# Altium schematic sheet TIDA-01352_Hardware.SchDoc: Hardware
size 431 x 279 mm; Date: Not shown in title block; ApprovedBy: Not shown in title block; CheckedBy: Not shown in title block; Author: Not shown in title block; CompanyName: Not shown in title block; DrawnBy: Sanjay Pithadia; Engineer: Sanjay Pithadia; Organization: Not shown in title block; Address1: Not shown in title block; Address2: Not shown in title block; Address3: Not shown in title block; Address4: Not shown in title block; DocumentNumber: 1; Revision: Use project parameter SCH_Rev; SheetNumber: 9; SheetTotal: 9; PageSetup: Record=PageOptions¦CenterHorizontal=True¦CenterVertical=True¦PrintScale=1.00¦XCorrection=1.00¦YCorrection=1.00¦PrintKind=0¦BorderSize=5000000¦LeftOffset=0¦BottomOffset=0¦Orientation=2¦PaperLength=1000¦PaperWidth=1000¦Scale=100¦PaperSource=15¦PrintQuality=600¦MediaType=1¦DitherType=10¦PaperKind=Letter¦PrintScaleMode=1
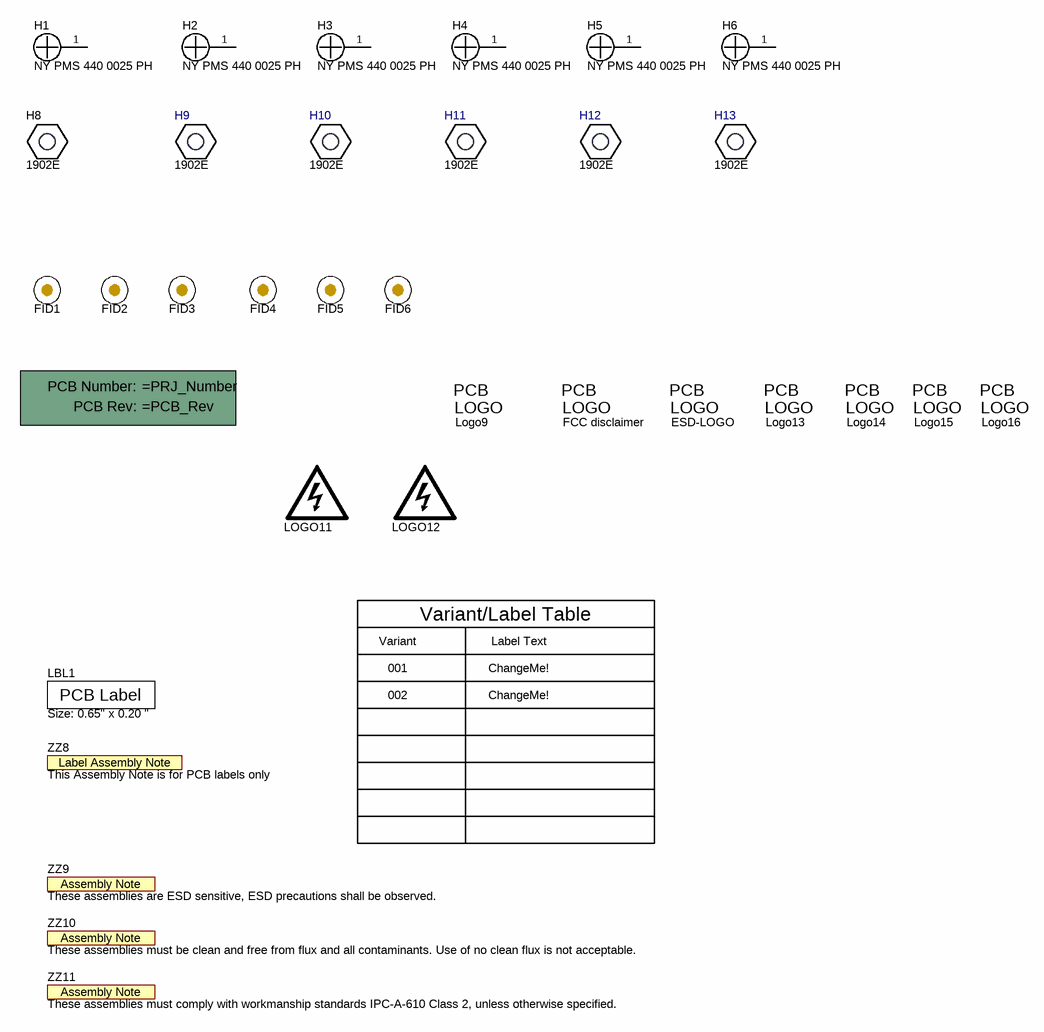
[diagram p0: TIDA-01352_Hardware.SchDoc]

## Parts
!PCB8  Printed Circuit Board  (value not drawn)  (mechanical)
ESD-LOGO  ESD Susceptible  [ESD_Overlay_medium]  (value not drawn)  (no BOM)
FID1  Fiducial  [Fiducial10-20]  (value not drawn)
FID2  Fiducial  [Fiducial10-20]  (value not drawn)
FID3  Fiducial  [Fiducial10-20]  (value not drawn)
FID4  Fiducial  [Fiducial10-20]  (value not drawn)
FID5  Fiducial  [Fiducial10-20]  (value not drawn)
FID6  Fiducial  [Fiducial10-20]  (value not drawn)
H1  NY PMS 440 0025 PH  [NY PMS 440 0025 PH]
H2  NY PMS 440 0025 PH  [NY PMS 440 0025 PH]
H3  NY PMS 440 0025 PH  [NY PMS 440 0025 PH]
H4  NY PMS 440 0025 PH  [NY PMS 440 0025 PH]
H5  NY PMS 440 0025 PH  [NY PMS 440 0025 PH]
H6  NY PMS 440 0025 PH  [NY PMS 440 0025 PH]
H8  1902E  [Keystone_1902E]
H9  1902E  [Keystone_1902E]
H10  1902E  [Keystone_1902E]
H11  1902E  [Keystone_1902E]
H12  1902E  [Keystone_1902E]
H13  1902E  [Keystone_1902E]
LBL1  Size: 0.65" x 0.20 "  [Label_650x200]
Logo9  EU RoHS Exempt Logo  [EURoHS_Exempt_60mil]  (value not drawn)  (no BOM)
Logo10  FCC disclaimer  [FCC_disclaimer]  (no BOM)
LOGO11  DANGER HIGH VOLTAGE  [IEC_HighVoltage_medium]  (value not drawn)  (no BOM)
LOGO12  DANGER HIGH VOLTAGE  [IEC_HighVoltage_medium]  (value not drawn)  (no BOM)
Logo13  CAUTION.  READ USER GUIDE BEFORE USE  [IEC_Caution_small]  (value not drawn)  (no BOM)
Logo14  CAUTION.  READ USER GUIDE BEFORE USE  [IEC_Caution_small]  (value not drawn)  (no BOM)
Logo15  CAUTION.  READ USER GUIDE BEFORE USE  [IEC_Caution_small]  (value not drawn)  (no BOM)
Logo16  CAUTION.  READ USER GUIDE BEFORE USE  [IEC_Caution_small]  (value not drawn)  (no BOM)
ZZ8  This Assembly Note is for PCB labels only  [AssemblyNoteLabel]  (no BOM)
ZZ9  These assemblies are ESD sensitive, ESD precautions shall be observed.  [AssemblyNote]  (no BOM)
ZZ10  These assemblies must be clean and free from flux and all contaminants. Use of no clean flux is not acceptable.  [AssemblyNote]  (no BOM)
ZZ11  These assemblies must comply with workmanship standards IPC-A-610 Class 2, unless otherwise specified.  [AssemblyNote]  (no BOM)

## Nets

Not connected (* = marked no-connect by the designer): H1 1; H2 1; H3 1; H4 1; H5 1; H6 1

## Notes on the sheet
- Variant
- Variant/Label Table
- Label Text
- 001
- 002
- ChangeMe!

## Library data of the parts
!PCB8 = PCB: Manufacturer: Any; SymbolCreator: a0412235
ESD-LOGO = ESD_Susceptible: ESD Susceptible Symbol; SymbolCreator: a0412235
FID1-FID6 = Fiducial: Fiducial mark.  There is nothing to buy or mount.; SymbolCreator: codlsc
H1-H6 = NY PMS 440 0025 PH: Machine Screw, Round, #4-40 x 1/4, Nylon, Philips panhead; Manufacturer: B&F Fastener Supply; CompType: Hardware; SymbolCreator: codlsc; U/M: EA
H8-H13 = 1902E: Standoff, Hex, 1"L #4-40 Nylon; Manufacturer: Keystone; SymbolCreator: a0412235; CompType: Hardware
LBL1 = THT-14-423-10: Thermal Transfer Printable Labels, 0.650" W x 0.200" H - 10,000 per roll; Manufacturer: Brady; SymbolCreator: a0412235; CompType: Label
Logo9 = EURoHS_Exempt: SymbolCreator: a0412235
Logo10 = FCC_disclaimer: SymbolCreator: codlsc
LOGO11 LOGO12 = IEC_HighVoltage: IEC 61010-1 High Voltage Warning; SymbolCreator: a0412235
Logo13-Logo16 = IEC_Caution: IEC 61010-1 Caution Warning; SymbolCreator: a0412235
ZZ8 = AssemblyNoteLabel: SymbolCreator: a0412235
ZZ9-ZZ11 = AssemblyNote: SymbolCreator: codlsc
